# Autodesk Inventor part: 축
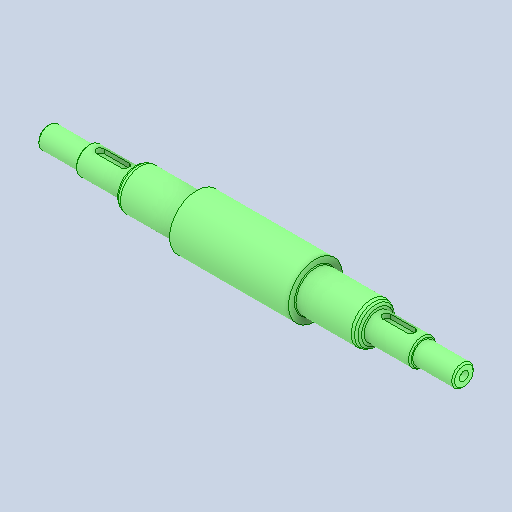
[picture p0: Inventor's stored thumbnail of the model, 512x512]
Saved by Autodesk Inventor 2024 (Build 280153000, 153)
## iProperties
Created: 2025-10
Part Number: 축
Material: 강철, 탄소
Document SubType Name: Modeling
Designer: EDU03
Density: 7.85 g/cm^3
Appearance: 기본값
Author: jhkim
Sending System: Autodesk Inventor 2026
Preprocessor: ST-DEVELOPER v20.1
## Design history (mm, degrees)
feature "솔리드1"
node "솔리드2"
